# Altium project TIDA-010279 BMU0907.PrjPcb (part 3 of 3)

## Sheet TIDA-010279 BMU_CAN MCU.SchDoc
size 558 x 431 mm; Date: Not shown in title block; ApprovedBy: Not shown in title block; CheckedBy: Not shown in title block; Author: Not shown in title block; CompanyName: Not shown in title block; Engineer: Not shown in title block; Organization: Not shown in title block; Address1: Not shown in title block; Address2: Not shown in title block; Address3: Not shown in title block; Address4: Not shown in title block; DocumentNumber: 1; Revision: Use project parameter SCH_Rev; SheetNumber: 4; SheetTotal: 4; PageSetup: Record=PageOptions¦CenterHorizontal=True¦CenterVertical=True¦PrintScale=1.00¦XCorrection=1.00¦YCorrection=1.00¦PrintKind=0¦BorderSize=5000000¦LeftOffset=0¦BottomOffset=0¦Orientation=2¦PaperLength=1000¦PaperWidth=1000¦Scale=100¦PaperSource=15¦PrintQuality=600¦MediaType=1¦DitherType=10¦PaperKind=Letter¦PrintScaleMode=1
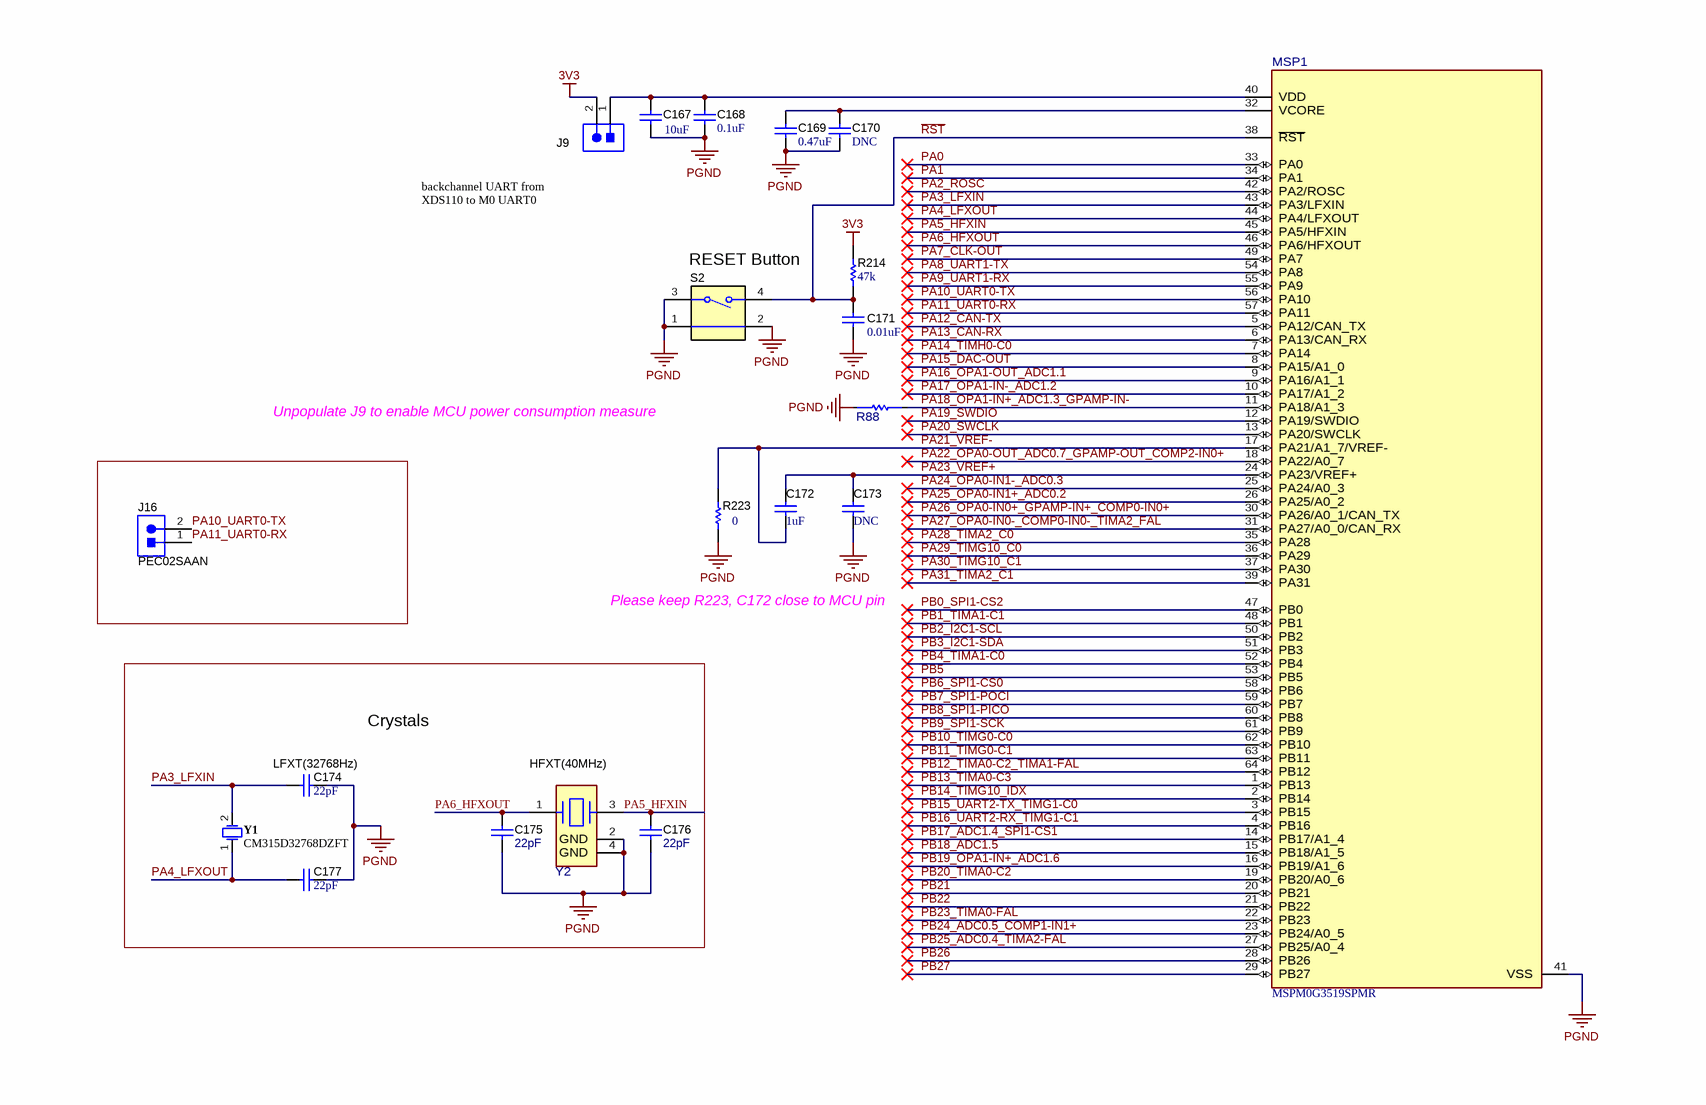
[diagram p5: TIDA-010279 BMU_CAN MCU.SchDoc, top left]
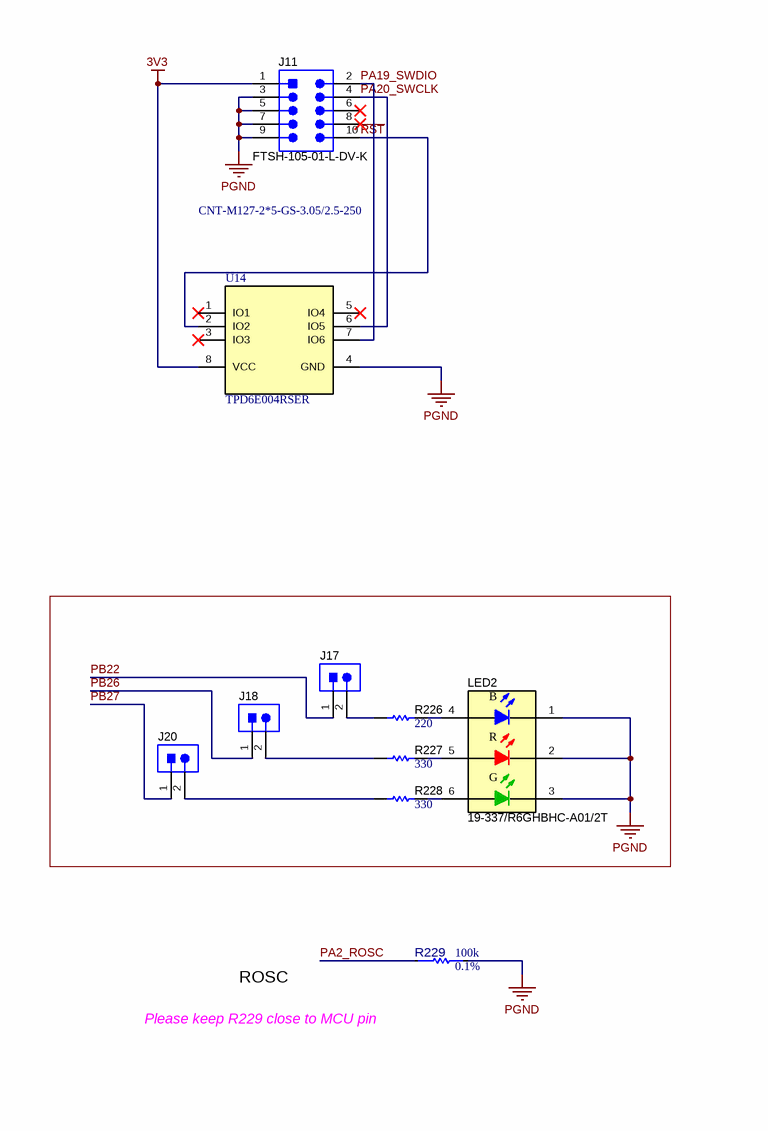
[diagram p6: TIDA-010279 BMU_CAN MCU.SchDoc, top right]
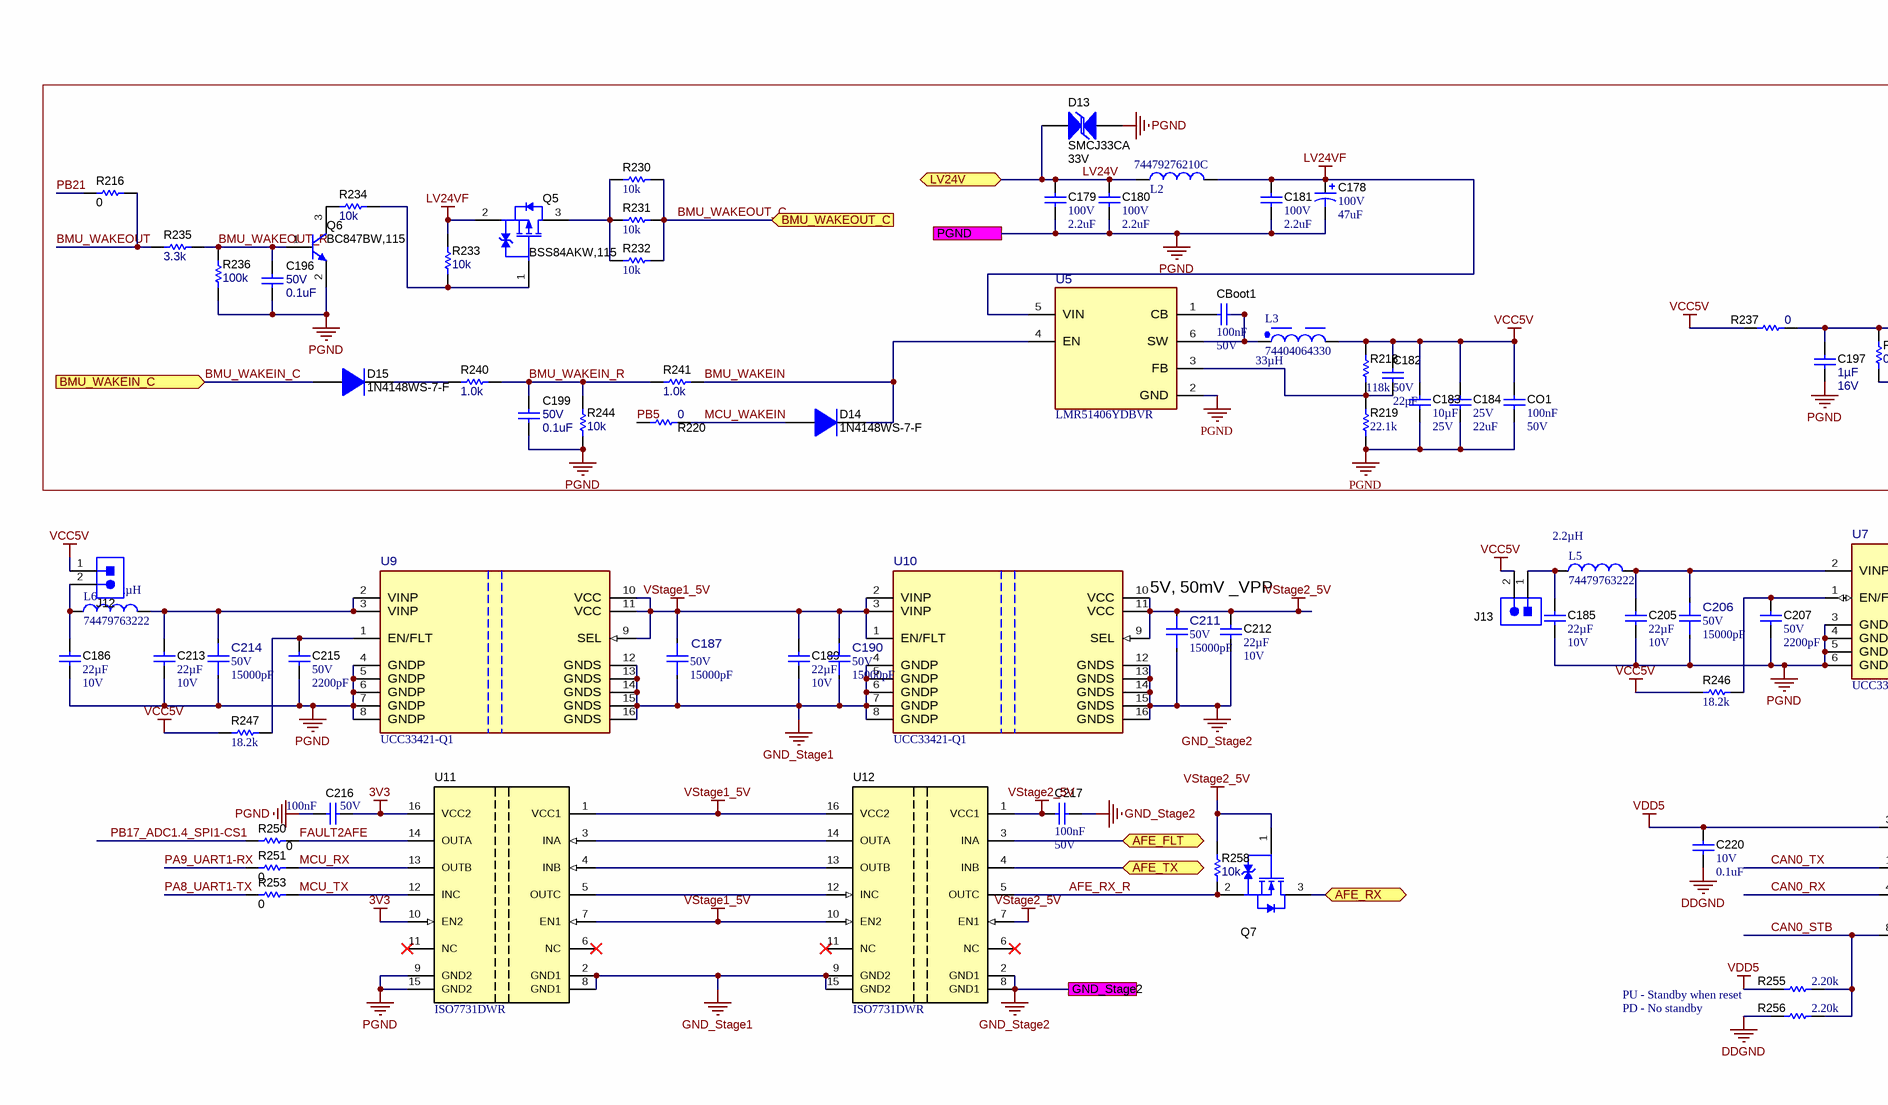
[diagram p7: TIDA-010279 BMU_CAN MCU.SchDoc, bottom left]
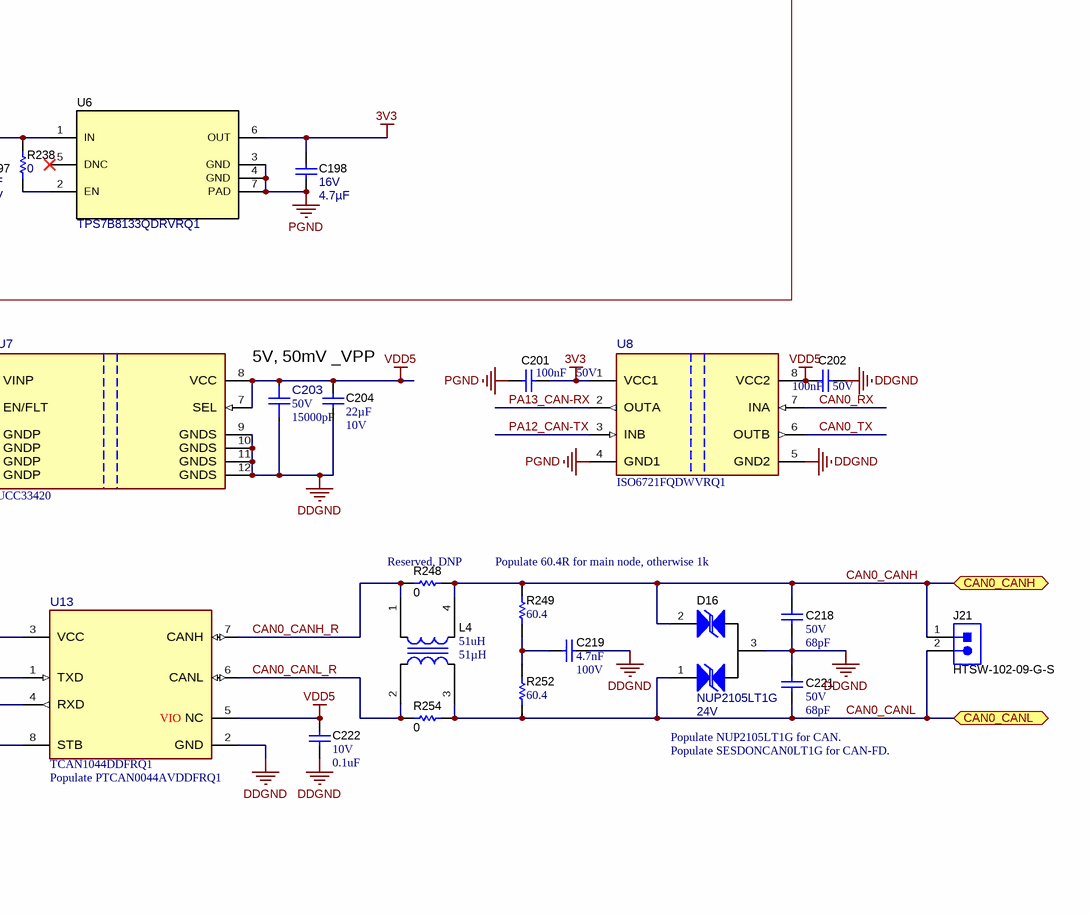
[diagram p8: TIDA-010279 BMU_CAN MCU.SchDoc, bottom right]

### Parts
C167  ValueDisplayed: 10uF  [0603]  (hidden comment: GRM188R60J106ME84)
C168  ValueDisplayed: 0.1uF  [0402]  (hidden comment: GRM155R61H104ME14D)
C169  ValueDisplayed: 0.47uF  [0402]  (hidden comment: GRM155R60J474KE19D)
C170  ValueDisplayed: DNC  [0402]  (hidden comment: GRM155R61H104ME14D)  (no BOM)
C171  ValueDisplayed: 0.01uF  [0402]  (hidden comment: GRM155R61C103KA01D)
C172  value 1uF  [0603]  (hidden comment: C1608X5R1E105K080AC)
C173  ValueDisplayed: DNC  [0603]  (hidden comment: C1608X5R1E105K080AC)  (no BOM)
C174  ValueDisplayed: 22pF  [0402]  (hidden comment: GRM1555C1H220JA01D)
C175  ValueDisplayed: 22pF  [0402]  (hidden comment: GRM1555C1H220JA01D)
C176  ValueDisplayed: 22pF  [0402]  (hidden comment: GRM1555C1H220JA01D)
C177  ValueDisplayed: 22pF  [0402]  (hidden comment: GRM1555C1H220JA01D)
C178  VDC_V: 100V  ValueDisplayed: 47uF  [Panasonic_H13]  (hidden comment: EEV-TG2A470Q)
C179  VDC_V: 100V  ValueDisplayed: 2.2uF  [1206_180]  (hidden comment: C3216X7S2A225K160AB)
C180  VDC_V: 100V  ValueDisplayed: 2.2uF  [1206_180]  (hidden comment: C3216X7S2A225K160AB)
C181  VDC_V: 100V  ValueDisplayed: 2.2uF  [1206_180]  (hidden comment: C3216X7S2A225K160AB)
C182  value 22pF  VDC_V: 50V  [0603]  (hidden comment: CGA3E2C0G1H220J080AA)
C183  Cap_F: 10µF  VDC_V: 25V  [0805_HV]  (hidden comment: GRM21BZ71E106KE15L)
C184  VDC_V: 25V  ValueDisplayed: 22uF  [1812_280]  (hidden comment: CGA8P1X7R1E226M250KC)
C185  Cap_F: 22µF  VDC_V: 10V  [0805_HV]  (hidden comment: GRM21BZ71A226ME15L)
C186  Cap_F: 22µF  VDC_V: 10V  [0805_HV]  (hidden comment: GRM21BZ71A226ME15L)
C187  VDC_V: 50V  ValueDisplayed: 15000pF  [FP-GCM155R71H153KA55D_0402-MFG]  (hidden comment: GCM155R71H153KA55D)
C189  Cap_F: 22µF  VDC_V: 10V  [0805_HV]  (hidden comment: GRM21BZ71A226ME15L)
C190  VDC_V: 50V  ValueDisplayed: 15000pF  [FP-GCM155R71H153KA55D_0402-MFG]  (hidden comment: GCM155R71H153KA55D)
C196  VDC_V: 50V  ValueDisplayed: 0.1uF  [0402]  (hidden comment: GCM155R71H104KE02D)
C197  Cap_F: 1µF  VDC_V: 16V  [0603]  (hidden comment: GCM188R71C105KA64D)
C198  VDC_V: 16V  ValueDisplayed: 4.7µF  [0603]  (hidden comment: GRT188R61C475KE13D)
C199  VDC_V: 50V  ValueDisplayed: 0.1uF  [0402]  (hidden comment: GCM155R71H104KE02D)
C201  Cap_F: 100nF  VDC_V: 50V  [0603]  (hidden comment: 06035C104KAT2A)
C202  Cap_F: 100nF  VDC_V: 50V  [0603]  (hidden comment: 06035C104KAT2A)
C203  VDC_V: 50V  ValueDisplayed: 15000pF  [FP-GCM155R71H153KA55D_0402-MFG]  (hidden comment: GCM155R71H153KA55D)
C204  Cap_F: 22µF  VDC_V: 10V  [0805_HV]  (hidden comment: GRM21BZ71A226ME15L)
C205  Cap_F: 22µF  VDC_V: 10V  [0805_HV]  (hidden comment: GRM21BZ71A226ME15L)
C206  VDC_V: 50V  ValueDisplayed: 15000pF  [FP-GCM155R71H153KA55D_0402-MFG]  (hidden comment: GCM155R71H153KA55D)
C207  VDC_V: 50V  ValueDisplayed: 2200pF  [0402]  (hidden comment: GCM155R71H222KA37D)
C211  VDC_V: 50V  ValueDisplayed: 15000pF  [FP-GCM155R71H153KA55D_0402-MFG]  (hidden comment: GCM155R71H153KA55D)
C212  Cap_F: 22µF  VDC_V: 10V  [0805_HV]  (hidden comment: GRM21BZ71A226ME15L)
C213  Cap_F: 22µF  VDC_V: 10V  [0805_HV]  (hidden comment: GRM21BZ71A226ME15L)
C214  VDC_V: 50V  ValueDisplayed: 15000pF  [FP-GCM155R71H153KA55D_0402-MFG]  (hidden comment: GCM155R71H153KA55D)
C215  VDC_V: 50V  ValueDisplayed: 2200pF  [0402]  (hidden comment: GCM155R71H222KA37D)
C216  Cap_F: 100nF  VDC_V: 50V  [0603]  (hidden comment: 06035C104KAT2A)
C217  Cap_F: 100nF  VDC_V: 50V  [0603]  (hidden comment: 06035C104KAT2A)
C218  VDC_V: 50V  ValueDisplayed: 68pF  [0603]  (hidden comment: GCM1885C1H680JA16D)
C219  Cap_F: 4.7nF  VDC_V: 100V  [0603]  (hidden comment: GCM188R72A472KA37D)
C220  VDC_V: 10V  ValueDisplayed: 0.1uF  [0402]  (hidden comment: GCM155R71A104KA55D)
C221  VDC_V: 50V  ValueDisplayed: 68pF  [0603]  (hidden comment: GCM1885C1H680JA16D)
C222  VDC_V: 10V  ValueDisplayed: 0.1uF  [0402]  (hidden comment: GCM155R71A104KA55D)
CBoot1  Cap_F: 100nF  VDC_V: 50V  [0603]  (hidden comment: 06035C104KAT2A)
CO1  Cap_F: 100nF  VDC_V: 50V  [0805_HV]  (hidden comment: 08055C104JAT2A)
D13  SMCJ33CA  value 33V  [SMC_Bi]
D14  1N4148WS-7-F  [SOD-323]
D15  1N4148WS-7-F  [SOD-323]
D16  NUP2105LT1G  value 24V  [SOT-23]
J9  90120-0122  [CONN_90120-0122]  (value not drawn)
J11  FTSH-105-01-L-DV-K  [Samtec_FTSH-105-01-x-DV-K]
J12  90120-0122  [CONN_90120-0122]  (value not drawn)
J13  90120-0122  [CONN_90120-0122]  (value not drawn)
J16  PEC02SAAN  [CONN_PEC02SAAN]
J17  90120-0122  [CONN_90120-0122]  (value not drawn)
J18  90120-0122  [CONN_90120-0122]  (value not drawn)
J20  90120-0122  [CONN_90120-0122]  (value not drawn)
J21  HTSW-102-09-G-S  [Samtec_HTSW-102-09-x-S]
L2  74479276210C  [WE-PMCI_0806_L2W1.6H1]
L3  74404064330  Inductance: 33µH  [WE-LQS_6045]
L4  value 51uH  ValueDisplayed: 51µH  [ACT45B_NoSilk]  (hidden comment: ACT45B-510-2P-TL003)
L5  74479763222  Inductance: 2.2µH  [WE-PMI_0603_L1.6W0.8H0.8]
L6  74479763222  Inductance: 2.2µH  [WE-PMI_0603_L1.6W0.8H0.8]
LED2  19-337/R6GHBHC-A01/2T  [19-337_RGB]
MSP1  PartNumber: MSPM0G3519SPMR  [PM0064A-MFG]  (hidden comment: MSPM0G3507SPM)
Q5  BSS84AKW,115  [SOT-323]
Q6  BC847BW,115  [SOT-323]
Q7  RE1C002UNTCL  [SC-89]  (value not drawn)
R88  ERJ-2GEJ473X  [FP-ERJ-2GEJ473X_0402-MFG]  (value not drawn)
R214  ValueDisplayed: 47k  [0402]  (hidden comment: CRCW040247K0JNED)
R216  ValueDisplayed: 0  [0402]  (hidden comment: CRCW04020000Z0ED)
R218  ValueDisplayed: 118k  [0402]  (hidden comment: CRCW0402118KFKED)
R219  ValueDisplayed: 22.1k  [0402]  (hidden comment: CRCW040222K1FKED)
R220  ValueDisplayed: 0  [0603]  (hidden comment: CRCW06030000Z0EA)
R223  value 0  [0603]  (hidden comment: RC0603JR-070RL)
R226  ValueDisplayed: 220  [0402]  (hidden comment: CRCW0402220RJNED)
R227  ValueDisplayed: 330  [0402]  (hidden comment: CRCW0402330RJNED)
R228  ValueDisplayed: 330  [0402]  (hidden comment: CRCW0402330RJNED)
R229  Tolerance_%: 0.1%  Res_ohm: 100k  [FP-ERA-2AEB104X_0402-MFG]  (hidden comment: ERA-2AEB104X)
R230  ValueDisplayed: 10k  [0603]  (hidden comment: CRCW060310K0JNEA)
R231  ValueDisplayed: 10k  [0603]  (hidden comment: CRCW060310K0JNEA)
R232  ValueDisplayed: 10k  [0603]  (hidden comment: CRCW060310K0JNEA)
R233  ValueDisplayed: 10k  [0402]  (hidden comment: CRCW040210K0JNED)
R234  ValueDisplayed: 10k  [0402]  (hidden comment: CRCW040210K0JNED)
R235  ValueDisplayed: 3.3k  [0402]  (hidden comment: CRCW04023K30JNED)
R236  ValueDisplayed: 100k  [0402]  (hidden comment: CRCW0402100KJNED)
R237  ValueDisplayed: 0  [0603]  (hidden comment: CRCW06030000Z0EA)
R238  ValueDisplayed: 0  [0603]  (hidden comment: CRCW06030000Z0EA)
R240  ValueDisplayed: 1.0k  [0402]  (hidden comment: CRCW04021K00JNED)
R241  ValueDisplayed: 1.0k  [0402]  (hidden comment: CRCW04021K00JNED)
R244  ValueDisplayed: 10k  [0402]  (hidden comment: CRCW040210K0JNED)
R246  ValueDisplayed: 18.2k  [0603]  (hidden comment: CRCW060318K2FKEA)
R247  ValueDisplayed: 18.2k  [0603]  (hidden comment: CRCW060318K2FKEA)
R248  ValueDisplayed: 0  [0402]  (hidden comment: CRCW04020000Z0ED)
R249  ValueDisplayed: 60.4  [1206]  (hidden comment: ERJ-8ENF60R4V)
R250  ValueDisplayed: 0  [0402]  (hidden comment: CRCW04020000Z0ED)
R251  ValueDisplayed: 0  [0402]  (hidden comment: CRCW04020000Z0ED)
R252  ValueDisplayed: 60.4  [1206]  (hidden comment: ERJ-8ENF60R4V)
R253  ValueDisplayed: 0  [0402]  (hidden comment: CRCW04020000Z0ED)
R254  ValueDisplayed: 0  [0402]  (hidden comment: CRCW04020000Z0ED)
R255  ValueDisplayed: 2.20k  [0402]  (hidden comment: ERJ-2RKF2201X)
R256  ValueDisplayed: 2.20k  [0402]  (hidden comment: ERJ-2RKF2201X)
R258  ValueDisplayed: 10k  [0402]  (hidden comment: CRCW040210K0JNED)
S2  1188E-1K2-V-TR  [SW_1188E]  (value not drawn)
U5  PartNumber: LMR51406YDBVR  [DBV0006A-MFG]  (hidden comment: LMR51410YDBVR)
U6  TPS7B8133QDRVRQ1  [DRV0006A]
U7  UCC33420  [RAQ0012B-MFG]
U8  ISO6721FQDWVRQ1  [DWV0008A-MFG]
U9  UCC33421-Q1  [DWX0016A-MFG]
U10  UCC33421-Q1  [DWX0016A-MFG]
U11  ISO7731DWR  [DW0016B_HV]
U12  ISO7731DWR  [DW0016B_HV]
U13  TCAN1044DDFRQ1  [DDF0008A-MFG]
U14  TPD6E004RSER  [RSE0008A]
Y1  CM315D32768DZFT  [CMHT-CM315D-2_V]
Y2  X1E0000210179  [FP-X1E0000210179_TSX-3225-MFG]  (value not drawn)

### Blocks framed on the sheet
Crystals: C174-C177 Y1 Y2

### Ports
AFE_FLT (bidir), AFE_RX (bidir), AFE_TX (bidir), BMU_WAKEIN_C (in), BMU_WAKEOUT_C (in), CAN0_CANH (bidir), CAN0_CANL (bidir), GND_Stage2, LV24V (bidir), PGND

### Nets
3V3: C198.1 C201.2 C216.1 J9.2 J11.1 R214.2 U6.6(OUT) U8.1(VCC1) U11.10(EN2) U11.16(VCC2) U14.8(VCC)
DDGND: C202.2 C203.1 C204.2 C218.2 C219.2 C220.1 C221.1 C222.2 D16.3 R256.2 U7.9(GNDS) U7.10(GNDS) U7.11(GNDS) U7.12(GNDS) U8.5(GND2) U13.2(GND)
GND_Stage1: C187.1 C189.2 C190.1 U9.12(GNDS) U9.13(GNDS) U9.14(GNDS) U9.15(GNDS) U9.16(GNDS) U10.4(GNDP) U10.5(GNDP) U10.6(GNDP) U10.7(GNDP) U10.8(GNDP) U11.2(GND1) U11.8(GND1) U12.9(GND2) U12.15(GND2)
GND_Stage2: C211.1 C212.2 C217.1 U10.12(GNDS) U10.13(GNDS) U10.14(GNDS) U10.15(GNDS) U10.16(GNDS) U12.2(GND1) U12.8(GND1) ; port GND_Stage2
LV24VF: C178.1(+) C181.1 L2.2 Q5.2(S) R233.2 U5.5(VIN)
PGND: C167.2 C168.2 C169.2 C170.2 C171.2 C173.2 C174.1 C175.1 C176.1 C177.1 C178.2(-) C179.2 C180.2 C181.2 C183.2 C184.2 C185.2 C186.2 C196.2 C197.2 C198.2 C199.2 C201.1 C205.2 C206.1 C207.2 C213.2 C214.1 C215.2 C216.2 CO1.2 D13.1 J11.3 J11.5 J11.7 J11.9 LED2.1(K) LED2.2(K) LED2.3(K) MSP1.41(VSS) Q6.2(E) R88.1 R219.1 R223.1 R229.2 R236.1 R244.1 S2.1 S2.2 S2.3 U5.2(GND) U6.3(GND) U6.4(GND) U6.7(PAD) U7.3(GNDP) U7.4(GNDP) U7.5(GNDP) U7.6(GNDP) U8.4(GND1) U9.4(GNDP) U9.5(GNDP) U9.6(GNDP) U9.7(GNDP) U9.8(GNDP) U11.9(GND2) U11.15(GND2) U14.4(GND) Y2.2(GND) Y2.4(GND) ; port PGND
VCC5V: C182.1 C183.1 C184.1 CO1.1 J12.1 J13.2 L3.2 R218.2 R237.1 R246.1 R247.1
VDD5: C202.1 C203.2 C204.1 C220.2 C222.1 R255.2 U7.7(SEL) U7.8(VCC) U8.8(VCC2) U13.3(VCC) U13.5(NC)
VStage1_5V: C187.2 C189.1 C190.2 U9.9(SEL) U9.10(VCC) U9.11(VCC) U10.1(EN/FLT) U10.2(VINP) U10.3(VINP) U11.1(VCC1) U11.7(EN1) U12.10(EN2) U12.16(VCC2)
VStage2_5V: C211.2 C212.1 C217.2 Q7.1(G) R258.2 U10.9(SEL) U10.10(VCC) U10.11(VCC) U12.1(VCC1) U12.7(EN1)
AFE_FLT: U12.3(INA) ; port AFE_FLT
AFE_RX: Q7.3(D) ; port AFE_RX
AFE_RX_R: Q7.2(S) R258.1 U12.5(OUTC)
AFE_TX: U12.4(INB) ; port AFE_TX
BMU_WAKEIN: D14.1(K) R241.2 U5.4(EN)
BMU_WAKEIN_C: D15.2(A) ; port BMU_WAKEIN_C
BMU_WAKEIN_R: C199.1 R240.2 R241.1 R244.2
BMU_WAKEOUT: R216.2 R235.1
BMU_WAKEOUT_C: R230.2 R231.2 R232.2 ; port BMU_WAKEOUT_C
BMU_WAKEOUT_R: C196.1 Q6.1(B) R235.2 R236.2
CAN0_CANH: C218.1 D16.2 J21.1 L4.4 R248.2 R249.2 ; port CAN0_CANH
CAN0_CANH_R: L4.1 R248.1 U13.7(CANH)
CAN0_CANL: C221.2 D16.1 J21.2 L4.3 R252.1 R254.2 ; port CAN0_CANL
CAN0_CANL_R: L4.2 R254.1 U13.6(CANL)
CAN0_RX: U8.7(INA) U13.4(RXD)
CAN0_STB: R255.1 R256.1 U13.8(STB)
CAN0_TX: U8.6(OUTB) U13.1(TXD)
FAULT2AFE: R250.1 U11.14(OUTA)
LV24V: C179.1 C180.1 D13.2 L2.1 ; port LV24V
MCU_RX: R251.2 U11.13(OUTB)
MCU_TX: R253.2 U11.12(INC)
MCU_WAKEIN: D14.2(A) R220.2
PA0: MSP1.33(PA0)
PA1: MSP1.34(PA1)
PA2_ROSC: MSP1.42(PA2/ROSC) R229.1
PA3_LFXIN: C174.2 MSP1.43(PA3/LFXIN) Y1.2
PA4_LFXOUT: C177.2 MSP1.44(PA4/LFXOUT) Y1.1
PA5_HFXIN: C176.2 MSP1.45(PA5/HFXIN) Y2.3
PA6_HFXOUT: C175.2 MSP1.46(PA6/HFXOUT) Y2.1
PA7_CLK-OUT: MSP1.49(PA7)
PA8_UART1-TX: MSP1.54(PA8) R253.1
PA9_UART1-RX: MSP1.55(PA9) R251.1
PA10_UART0-TX: J16.2 MSP1.56(PA10)
PA11_UART0-RX: J16.1 MSP1.57(PA11)
PA12_CAN-TX: MSP1.5(PA12/CAN_TX) U8.3(INB)
PA13_CAN-RX: MSP1.6(PA13/CAN_RX) U8.2(OUTA)
PA14_TIMH0-C0: MSP1.7(PA14)
PA15_DAC-OUT: MSP1.8(PA15/A1_0)
PA16_OPA1-OUT_ADC1.1: MSP1.9(PA16/A1_1)
PA17_OPA1-IN-_ADC1.2: MSP1.10(PA17/A1_2)
PA18_OPA1-IN+_ADC1.3_GPAMP-IN-: MSP1.11(PA18/A1_3) R88.2
PA19_SWDIO: J11.2 MSP1.12(PA19/SWDIO) U14.7(IO6)
PA20_SWCLK: J11.4 MSP1.13(PA20/SWCLK) U14.6(IO5)
PA21_VREF-: C172.2 MSP1.17(PA21/A1_7/VREF-) R223.2
PA22_OPA0-OUT_ADC0.7_GPAMP-OUT_COMP2-IN0+: MSP1.18(PA22/A0_7)
PA23_VREF+: C172.1 C173.1 MSP1.24(PA23/VREF+)
PA24_OPA0-IN1-_ADC0.3: MSP1.25(PA24/A0_3)
PA25_OPA0-IN1+_ADC0.2: MSP1.26(PA25/A0_2)
PA26_OPA0-IN0+_GPAMP-IN+_COMP0-IN0+: MSP1.30(PA26/A0_1/CAN_TX)
PA27_OPA0-IN0-_COMP0-IN0-_TIMA2_FAL: MSP1.31(PA27/A0_0/CAN_RX)
PA28_TIMA2_C0: MSP1.35(PA28)
PA29_TIMG10_C0: MSP1.36(PA29)
PA30_TIMG10_C1: MSP1.37(PA30)
PA31_TIMA2_C1: MSP1.39(PA31)
PB0_SPI1-CS2: MSP1.47(PB0)
PB1_TIMA1-C1: MSP1.48(PB1)
PB2_I2C1-SCL: MSP1.50(PB2)
PB3_I2C1-SDA: MSP1.51(PB3)
PB4_TIMA1-C0: MSP1.52(PB4)
PB5: MSP1.53(PB5) R220.1
PB6_SPI1-CS0: MSP1.58(PB6)
PB7_SPI1-POCI: MSP1.59(PB7)
PB8_SPI1-PICO: MSP1.60(PB8)
PB9_SPI1-SCK: MSP1.61(PB9)
PB10_TIMG0-C0: MSP1.62(PB10)
PB11_TIMG0-C1: MSP1.63(PB11)
PB12_TIMA0-C2_TIMA1-FAL: MSP1.64(PB12)
PB13_TIMA0-C3: MSP1.1(PB13)
PB14_TIMG10_IDX: MSP1.2(PB14)
PB15_UART2-TX_TIMG1-C0: MSP1.3(PB15)
PB16_UART2-RX_TIMG1-C1: MSP1.4(PB16)
PB17_ADC1.4_SPI1-CS1: MSP1.14(PB17/A1_4) R250.2
PB18_ADC1.5: MSP1.15(PB18/A1_5)
PB19_OPA1-IN+_ADC1.6: MSP1.16(PB19/A1_6)
PB20_TIMA0-C2: MSP1.19(PB20/A0_6)
PB21: MSP1.20(PB21) R216.1
PB22: J17.1 MSP1.21(PB22)
PB23_TIMA0-FAL: MSP1.22(PB23)
PB24_ADC0.5_COMP1-IN1+: MSP1.23(PB24/A0_5)
PB25_ADC0.4_TIMA2-FAL: MSP1.27(PB25/A0_4)
PB26: J18.1 MSP1.28(PB26)
PB27: J20.1 MSP1.29(PB27)
~{RST}: C171.1 J11.10 MSP1.38(~{RST}) R214.1 S2.4 U14.2(IO2)
NetC167_1: C167.1 C168.1 J9.1 MSP1.40(VDD)
NetC169_1: C169.1 C170.1 MSP1.32(VCORE)
NetC182_2: C182.2 R218.1 R219.2 U5.3(FB)
NetC185_1: C185.1 J13.1 L5.1
NetC186_1: C186.1 J12.2 L6.1
NetC197_1: C197.1 R237.2 R238.2 U6.1(IN)
NetC205_1: C205.1 C206.2 L5.2 U7.2(VINP)
NetC207_1: C207.1 R246.2 U7.1(EN/FLT)
NetC213_1: C213.1 C214.2 L6.2 U9.2(VINP) U9.3(VINP)
NetC215_1: C215.1 R247.2 U9.1(EN/FLT)
NetC219_1: C219.1 R249.1 R252.2
NetCBoot1_1: CBoot1.1 U5.1(CB)
NetCBoot1_2: CBoot1.2 L3.1 U5.6(SW)
NetD15_1: D15.1(K) R240.1
NetJ17_2: J17.2 R226.1
NetJ18_2: J18.2 R227.1
NetJ20_2: J20.2 R228.1
NetLED2_4: LED2.4(A) R226.2
NetLED2_5: LED2.5(A) R227.2
NetLED2_6: LED2.6(A) R228.2
NetQ5_1: Q5.1(G) R233.1 R234.1
NetQ5_3: Q5.3(D) R230.1 R231.1 R232.1
NetQ6_3: Q6.3(C) R234.2
NetR238_1: R238.1 U6.2(EN)
NetU11_3: U11.3(INA) U12.14(OUTA)
NetU11_4: U11.4(INB) U12.13(OUTB)
NetU11_5: U11.5(OUTC) U12.12(INC)

Not connected (* = marked no-connect by the designer): J11 6* 8*; U6 5(DNC)*; U11 6(NC)* 11(NC)*; U12 6(NC)* 11(NC)*; U14 1(IO1)* 3(IO3)* 5(IO4)*

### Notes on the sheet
- CNT-M127-2*5-GS-3.05/2.5-250
- backchannel UART from XDS110 to M0 UART0
- (near S2) RESET Button
- Unpopulate J9 to enable MCU power consumption measure
- Please keep R223, C172 close to MCU pin
- (near C174) LFXT(32768Hz)
- HFXT(40MHz)
- Please keep R229 close to MCU pin
- ROSC
- 5V, 50mV _VPP
- (near R248) Reserved, DNP
- (near R249) Populate 60.4R for main node, otherwise 1k
- (near U13) VIO
- (near U13) Populate PTCAN0044AVDDFRQ1
- Populate NUP2105LT1G for CAN.
- Populate SESDONCAN0LT1G for CAN-FD.
- PU - Standby when reset
- PD - No standby

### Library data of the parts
C167 = CMP-0007304-5: CAP, CERM, 10 uF, 6.3 V, +/- 20%, X5R, 0603; Manufacturer: MuRata; TaMin_C: -55°C; Polarized: N; SizeAreaWB_mm2: 4.68; Value1: Unknown; U/M: EA; Value: 10uF; TaMax_C: 85°C; SizeZ_mm: 1; SizeX_mm: 1.6; SizeY_mm: 0.8; Value2: 6.3V; SizeArea_mm2: 1.28; Cap_F: 10µF; AEC Category: Q200
C168 C170 = CMP-0006614-2: CAP, CERM, 0.1 uF, 50 V, +/- 20%, X5R, 0402; Manufacturer: MuRata; TaMin_C: -55°C; Polarized: N; SizeAreaWB_mm2: 3; Value1: Unknown; U/M: EA; Value: 0.1uF; TaMax_C: 85°C; SizeZ_mm: 0.6; SizeX_mm: 1; SizeY_mm: 0.5; Value2: 50V; Cap_F: 100nF; AEC Category: Q200
C169 = CMP-0006551-2: CAP, CERM, 0.47 uF, 6.3 V, +/- 10%, X5R, 0402; Manufacturer: MuRata; TaMin_C: -55°C; Polarized: N; SizeAreaWB_mm2: 3; Value1: Unknown; U/M: EA; Value: 0.47uF; TaMax_C: 85°C; SizeZ_mm: 0.6; SizeX_mm: 1; SizeY_mm: 0.5; Value2: 6.3V; Cap_F: 470nF; AEC Category: Q200
C171 = CMP-0006590-2: CAP, CERM, 0.01 uF, 16 V, +/- 10%, X5R, 0402; Manufacturer: MuRata; TaMin_C: -55°C; Polarized: N; SizeAreaWB_mm2: 3; Value1: Unknown; U/M: EA; Value: 0.01uF; TaMax_C: 85°C; SizeZ_mm: 0.6; SizeX_mm: 1; SizeY_mm: 0.5; Value2: 16V; Cap_F: 10nF; AEC Category: Q200
C172 = CMP-0007006-5: CAP, CERM, 1 uF, 25 V, +/- 10%, X5R, 0603; Manufacturer: TDK; TaMin_C: -55°C; Polarized: N; SizeAreaWB_mm2: 4.68; Value1: Unknown; U/M: EA; TaMax_C: 85°C; SizeZ_mm: 1; SizeX_mm: 1.6; SizeY_mm: 0.8; Value2: 25V; SizeArea_mm2: 1.28; Cap_F: 1µF; AEC Category: Q200; ValueDisplayed: DNC
C173 = CMP-0007006-5: CAP, CERM, 1 uF, 25 V, +/- 10%, X5R, 0603; Manufacturer: TDK; TaMin_C: -55°C; Polarized: N; SizeAreaWB_mm2: 4.68; Value1: Unknown; U/M: EA; Value: 1uF; TaMax_C: 85°C; SizeZ_mm: 1; SizeX_mm: 1.6; SizeY_mm: 0.8; Value2: 25V; SizeArea_mm2: 1.28; Cap_F: 1µF; AEC Category: Q200
C174-C177 = CMP-0006439-2: CAP, CERM, 22 pF, 50 V, +/- 5%, C0G/NP0, 0402; Manufacturer: MuRata; TaMin_C: -55°C; Polarized: N; SizeAreaWB_mm2: 3; Value1: Unknown; U/M: EA; Value: 22pF; TaMax_C: 125°C; SizeZ_mm: 0.6; SizeX_mm: 1; SizeY_mm: 0.5; Value2: 50V; AEC Category: Q200
C178 = CMP-0011227-2: CAP, AL, 47 uF, 100 V, +/- 20%, 0.42 ohm, AEC-Q200 Grade 1, SMD; Manufacturer: Panasonic; TaMin_C: -40°C; ESR_ohm: 4.2d; Polarized: Y; SizeAreaWB_mm2: 240.25; U/M: EA; Value: 47uF; TaMax_C: 125°C; SizeZ_mm: 14; SizeX_mm: 13.5; Cap_Case: 12.5x13.5mm; SizeArea_mm2: 182.25; CompType: Capacitor; Cap_F: 47µF; IRMS_A: 2.5dA; AEC Grade: 1; AEC Category: Q200
C179-C181 = CMP-0008724-2: CAP, CERM, 2.2 uF, 100 V, +/- 10%, X7S, 1206; Manufacturer: TDK; TaMin_C: -55°C; ESR_ohm: 5.718m; Polarized: N; SizeAreaWB_mm2: 10.92; Value1: 0.005718 ohm; U/M: EA; Value: 2.2uF; TaMax_C: 125°C; SizeZ_mm: 1.8; SizeX_mm: 3.2; SizeY_mm: 1.6; SizeArea_mm2: 5.12; Cap_F: 2.2µF; IRMS_A: 3.03632A; AEC Category: Q200
C182 = CMP-0007071-4: CAP, CERM, 22 pF, 50 V, +/- 5%, C0G/NP0, AEC-Q200 Grade 1, 0603; Manufacturer: TDK; TaMin_C: -55°C; Polarized: N; SizeAreaWB_mm2: 4.68; Value1: Unknown; U/M: EA; TaMax_C: 125°C; SizeZ_mm: 1; SizeX_mm: 1.6; SizeY_mm: 0.8; SizeArea_mm2: 1.28; AEC Qualified: Y; AEC Category: Q200
C183 = CMP-0008378-2: CAP, CERM, 10 uF, 25 V, +/- 10%, X7R, 0805; Manufacturer: MuRata; TaMin_C: -55°C; Polarized: N; SizeAreaWB_mm2: 6.75; Value1: Unknown; U/M: EA; Value: 10uF; TaMax_C: 125°C; SizeZ_mm: 1.45; SizeX_mm: 2; SizeY_mm: 1.25; Cap_Case: 0805; SizeArea_mm2: 2.5; AEC Category: Q200
C184 = CMP-0009402-2: CAP, CERM, 22 uF, 25 V, +/- 20%, X7R, AEC-Q200 Grade 1,; Manufacturer: TDK; TaMin_C: -55°C; ESR_ohm: 2.434m; Polarized: N; SizeAreaWB_mm2: 23.1; Value1: 0.002434 ohm; U/M: EA; Value: 22uF; TaMax_C: 125°C; SizeZ_mm: 2.8; SizeX_mm: 4.5; SizeY_mm: 3.2; SizeArea_mm2: 14.4; AEC Qualified: Y; Cap_F: 22µF; IRMS_A: 4.91649A; AEC Grade: 1; AEC Category: Q200
C185 C186 C189 C204 C205 C212 C213 = CMP-0008377-2: CAP, CERM, 22 uF, 10 V, +/- 20%, X7R, 0805; Manufacturer: MuRata; SizeY_mm: 1.25; Cap_Case: 0805; SizeArea_mm2: 2.5; AEC Qualified: N; AEC Category: Q200; ValueDisplayed: 22uF; TaMin_C: -55°C; SizeAreaWB_mm2: 6.75; Value1: Unknown; U/M: EA; Value: 22uF; TaMax_C: 125°C; SizeZ_mm: 1.45; SizeX_mm: 2
C187 C190 C203 C206 C211 C214 = CMP-0090630-1: 0.015µF ±10% 50V Ceramic Capacitor X7R 0402 (1005 Metric); Manufacturer: Murata; SizeZ_mm: 0.55mm; AEC Qualified: Yes; AEC Grade: Grade 1; Value: 15nF; TempCo: 15%
C196 C199 = CMP-0006356-2: CAP, CERM, 0.1 uF, 50 V, +/- 10%, X7R, AEC-Q200 Grade 1, 0402; Manufacturer: MuRata; TaMin_C: -55°C; Polarized: N; SizeAreaWB_mm2: 3; Value1: Unknown; U/M: EA; Value: 0.1uF; TaMax_C: 125°C; SizeZ_mm: 0.6; SizeX_mm: 1; SizeY_mm: 0.5; AEC Qualified: Y; Cap_F: 100nF; AEC Category: Q200
C197 = CMP-0007136-5: CAP, CERM, 1 uF, 16 V, +/- 10%, X7R, AEC-Q200 Grade 1, 0603; Manufacturer: MuRata; TaMin_C: -55°C; Polarized: N; SizeAreaWB_mm2: 4.68; Value1: Unknown; U/M: EA; Value: 1uF; TaMax_C: 125°C; SizeZ_mm: 1; SizeX_mm: 1.6; SizeY_mm: 0.8; SizeArea_mm2: 1.28; AEC Qualified: Y; AEC Category: Q200
C198 = CMP-0081052-1: CAP, CERM, 4.7 µF, 16 V,+/- 10%, X5R, AEC-Q200 Grade 3, 0603; Manufacturer: MuRata; SizeAreaWB_mm2: 4.68; SizeArea_mm2: 1.28; AEC Qualified: Y; AEC Category: Q200; Value: 4.7uF; TaMax_C: 85°C; SizeZ_mm: 1; AEC Grade: 3; Polarized: N; TaMin_C: -55°C; SizeY_mm: 0.8; U/M: EA; SizeX_mm: 1.6
C201 C202 C216 C217 CBoot1 = CMP-0006802-4: CAP, CERM, 0.1 uF, 50 V, +/- 10%, X7R, 0603; Manufacturer: AVX; TaMin_C: -55°C; Polarized: N; SizeAreaWB_mm2: 4.68; Value1: Unknown; U/M: EA; Value: 0.1uF; TaMax_C: 125°C; SizeZ_mm: 1; SizeX_mm: 1.6; SizeY_mm: 0.8; SizeArea_mm2: 1.28; AEC Category: Q200
C207 C215 = CMP-0006357-2: CAP, CERM, 2200 pF, 50 V, +/- 10%, X7R, AEC-Q200 Grade 1, 0402; Manufacturer: MuRata; TaMin_C: -55°C; Polarized: N; SizeAreaWB_mm2: 3; Value1: Unknown; U/M: EA; Value: 2200pF; TaMax_C: 125°C; SizeZ_mm: 0.6; SizeX_mm: 1; SizeY_mm: 0.5; AEC Qualified: Y; Cap_F: 2.2nF; AEC Category: Q200
C218 C221 = CMP-0007129-4: CAP, CERM, 68 pF, 50 V, +/- 5%, C0G/NP0, AEC-Q200 Grade 1, 0603; Manufacturer: MuRata; TaMin_C: -55°C; Polarized: N; SizeAreaWB_mm2: 4.68; Value1: Unknown; U/M: EA; Value: 68pF; TaMax_C: 125°C; SizeZ_mm: 1; SizeX_mm: 1.6; SizeY_mm: 0.8; SizeArea_mm2: 1.28; AEC Qualified: Y; AEC Category: Q200
C219 = CMP-0079247-1: CAP, CERM, 4700 pF, 100 V,+/- 10%, X7R, AEC-Q200 Grade 1, 0603; Manufacturer: MuRata; SizeAreaWB_mm2: 4.68; SizeArea_mm2: 1.28; AEC Qualified: Y; AEC Category: Q200; Value: 4700pF; TaMax_C: 125°C; SizeZ_mm: 1; Polarized: N; TaMin_C: -55°C; SizeY_mm: 0.8; U/M: EA; SizeX_mm: 1.6
C220 C222 = CMP-0006350-2: CAP, CERM, 0.1 uF, 10 V, +/- 10%, X7R, AEC-Q200 Grade 1, 0402; Manufacturer: MuRata; TaMin_C: -55°C; Polarized: N; SizeAreaWB_mm2: 3; Value1: Unknown; U/M: EA; Value: 0.1uF; TaMax_C: 125°C; SizeZ_mm: 0.6; SizeX_mm: 1; SizeY_mm: 0.5; AEC Qualified: Y; Cap_F: 100nF; AEC Category: Q200
CO1 = CMP-0007631-2: CAP, CERM, 0.1 uF, 50 V, +/- 5%, X7R, 0805; Manufacturer: AVX; TaMin_C: -55°C; ESR_ohm: 0.024; Polarized: N; SizeAreaWB_mm2: 6.75; Value1: 0.024 ohm; U/M: EA; Value: 0.1uF; TaMax_C: 125°C; SizeZ_mm: 1.45; SizeX_mm: 2; SizeY_mm: 1.25; Cap_Case: 0805; SizeArea_mm2: 2.5; AEC Category: Q200
D13 = CMP-0005695-3: Diode, TVS, Bi, 33 V, SMC; Manufacturer: Littelfuse; SizeZ_mm: 2.6; Ppk: 1.5kW; Value1: 1500W; AEC Category: Q101; SizeArea_mm2: 50.5686; SizeX_mm: 8.13; SizeAreaWB_mm2: 83.2686; SizeY_mm: 6.22
D14 D15 = CMP-0079597-2: Diode, Switching, 75 V, 0.15 A, AEC-Q101, SOD-323; Manufacturer: Diodes Inc.; SizeX_mm: 2.7; Vf_V: 1.25V; AEC Qualified: Y; SizeArea_mm2: 3.645; AEC Category: Q101; SizeAreaWB_mm2: 8.695; Io_A: 150mA; SizeZ_mm: 1; Value1: 0.15A; SizeY_mm: 1.35; TJmax_C: 150°C; Vr_V: 75V; Value: 75V
D16 = CMP-0005919-3: Diode, TVS, Bi, 24 V, SOT-23; Manufacturer: ON Semiconductor; Value1: 350W; SizeAreaWB_mm2: 14; SizeY_mm: 3; SizeZ_mm: 1.1; SizeX_mm: 2.5; AEC Category: Q101; SizeArea_mm2: 7.5
J9 J12 J13 J17 J18 J20 = CMP-0055312-1: Header, 100mil, 2x1, Tin, TH; Manufacturer: Molex; CNHeader: TRUE; Green_Lifecycle: Active; Green_REACh: Passed; CT: FALSE
J11 = CMP-0075634-2: Header(Shrouded), 1.27mm, 5x2, Gold, SMT; Manufacturer: Samtec; Pitch_mm: 1.27; Gender: Male; Cert_CSA: Y; Current_A: 3.3A; Row_Count: 2
J16 = CMP-0002337-1: Header, 100mil, 2x1, Tin, TH; Manufacturer: Sullins Connector Solutions; CNHeader: TRUE; Current_A: 3A; Green_Lifecycle: Not Set; Shrouded: N; Gender: Male; Green_REACh: Incomplete; Voltage_V: 1.8kV; Row_Count: 1; Pitch_mm: 2.54; CT: FALSE; Cert_UL: Y
J21 = CMP-0075626-1: Header, 100mil, 2x1, Gold, TH; Manufacturer: Samtec; Pitch_mm: 2.54; Gender: Male; Cert_CSA: Y; CT: False; Row_Count: 1
L2 = CMP-0100947-1: WE-PMCI SMT Power Molded Chip Inductor, size 0806, 1uH, 4.4A, 60mOhm; Manufacturer: Wurth Elektronik; Case/Size Code: 0806; DC Resistance: 55mOhm; Saturation Current: 4.25A; Self Resonant Frequency: 95MHz; Type: Low RDC
L3 = CMP-1354-00075-2: NexarPartId: 46948302; Manufacturer: Wurth Elektronik; Tolerance: 20%; Test Frequency: 100kHz; Saturation Current: 1.8A; DC Resistance (DCR): 137mΩ; Max DC Current: 1.45A; Self Resonant Frequency: 12MHz; Series Resistance: 178.1mΩ; Shielding: Shielded; Core Material: Ferrite
L4 = CMP-0076845-1: Coupled inductor, 51 µH, 0.2 A, 1 ohm, AEC-Q200 Grade 0, SMD; Manufacturer: TDK; SizeAreaWB_mm2: 23.1; SizeArea_mm2: 14.4; AEC Qualified: Y; AEC Category: Q200; SizeZ_mm: 3.0; Green_REACh: Passed; AEC Grade: 0; SizeY_mm: 3.2; Green_Lifecycle: Active; DCR_ohm: 1; SizeX_mm: 4.5
L5 L6 = CMP-1392-00025-2: NexarPartId: 38797936; Manufacturer: Wurth Elektronik; DC Resistance (DCR): 300mΩ; Current Rating: 550mA
LED2 = CMP-0074720-2: LED, RGB, TH; Manufacturer: Everlight; Io_A: 25mA; Vr_V: 5V; Tjmax_C: 85°C; Angle: 120.0; Ir_A: 50µA; Vf_V: 3.8V
MSP1 = CMP-0093960-1: Mixed-Signal Microcontrollers With CAN-FD Interface LQFP64; Manufacturer: Texas Instruments; Number Of I2C Channels: 2; Frequency_Fixed: 80MHz; Number Of Cores: 1; Number Of Pwm Channels: 14; Data Bus Width: 32bits; Standoff Height: 0.05mm; SizeZ_mm: 1.6mm; Number Of I/Os: 60; Memory Type: FLASH; Min Supply Voltage: 1.62V; Number Of Adc Channels: 16; Memory Size: 128KBytes; TJmax_C: +130°C; Number Of Uart Channels: 4; Number Of Timers/Counters: 7; Max Supply Voltage: 3.6V; TaMin_C: -40°C; Core Architecture: ARM Cortex-M0+; Interface: I2C,SPI,UART,CAN,LIN,IrDA,SMBus; Ram Size: 32KBytes; AEC Qualified: No; TaMax_C: +125°C
Q5 = CMP-0000013-4: MOSFET, P-CH, -50 V, -0.15 A, AEC-Q101, SOT-323; Manufacturer: Nexperia; Alternate Manufacturer: None; AEC Category: Q101; SizeY_mm: 2.2; Value: -50V; ChMode: Enhancement; ChType: P; QgTyp_nC: 0.26; IdsMax_A: -150mA; Value2: 0.26 nC; SizeZ_mm: 1.1; SizeAreaWB_mm2: 10.24; AEC Qualified: Y; Vgs_V: -20V; SizeArea_mm2: 4.84
Q6 = CMP-0000486-2: Transistor, NPN, 45 V, 0.1 A, AEC-Q101, SOT-323; Manufacturer: NXP Semiconductor; TaMax_C: 150°C; Value2: 800; Value1: 0.1 A; Vcesat1_V: 90mV; SizeX_mm: 2.2; TaMin_C: -65°C; IcRated_A: 1dA; CompType: BJT; SizeZ_mm: 1.1; AEC Qualified: Y; Value: 45 V; SizeArea_mm2: 4.84; NPN: 1; Vceo_V: 45V; PNP: 0; AEC Category: Q101; SizeAreaWB_mm2: 10.24; U/M: EA
Q7 = CMP-0086180-1: MOSFET, N-CH, 20 V, 0.2 A, AEC-Q101, SC-89; Alternate Manufacturer: None; Manufacturer: Rohm; AEC Category: Q101; Value: 20V; SizeY_mm: 1.6; Vgs_V: 8V; SizeArea_mm2: 2.56; SizeAreaWB_mm2: 6.76; Value2: ? nC; ChMode: Enhancement; ChType: N; Value1: ? ohm; SizeZ_mm: 0.8; AEC Qualified: Y; IdsMax_A: 200mA
R88 = CMP-0122885-1: 47 kOhms ±5% 0.1W, 1/10W Chip Resistor 0402 (1005 Metric) Automotive AEC-Q200 Thick Film; Manufacturer: Panasonic; AEC Grade: Grade 0; AEC Qualified: Yes; Power_W: 100mW; Res_ohm: 47k; SizeZ_mm: 0.4mm; TempCo: 200ppm/°C; VDC_V: 50V; Value: 47k
R214 = CMP-0026935-3: RES, 47 k, 5%, 0.063 W, AEC-Q200 Grade 0, 0402; Manufacturer: Vishay-Dale; Power_W: 63mW; TempCo: 200 ppm/C; Value_Code: 47k0; Value: 47k; EIA_Code: E24; SizeX_mm: 1; SizeY_mm: 0.5; SizeZ_mm: 0.6; Value2: 0.063W; AEC Qualified: Y; VDC_V: 50V; AEC Category: Q200; AEC Grade: 0
R216 R248 R250 R251 R253 R254 = CMP-0026822-3: RES, 0, 5%, 0.063 W, AEC-Q200 Grade 0, 0402; Manufacturer: Vishay-Dale; Power_W: 63mW; TempCo: 200 ppm/C; Value_Code: 0000; Value: 0; EIA_Code: E24; SizeX_mm: 1; SizeY_mm: 0.5; SizeZ_mm: 0.6; Value2: 0.063W; AEC Qualified: Y; VDC_V: 50V; AEC Category: Q200
R218 = CMP-0025973-3: RES, 118 k, 1%, 0.063 W, AEC-Q200 Grade 0, 0402; Manufacturer: Vishay-Dale; Power_W: 63mW; TempCo: 100 ppm/C; Value: 118k; EIA_Code: E96; SizeX_mm: 1; SizeY_mm: 0.5; SizeZ_mm: 0.6; Value2: 0.063W; AEC Qualified: Y; VDC_V: 50V; AEC Category: Q200; AEC Grade: 0
R219 = CMP-0026178-2: RES, 22.1 k, 1%, 0.063 W, AEC-Q200 Grade 0, 0402; Manufacturer: Vishay-Dale; Power_W: 63mW; TempCo: 100 ppm/C; Value_Code: 22k1; Value: 22.1k; EIA_Code: E96; SizeX_mm: 1; SizeY_mm: 0.5; SizeZ_mm: 0.6; Value2: 0.063W; AEC Qualified: Y; VDC_V: 50V; AEC Category: Q200; AEC Grade: 0
R220 R237 R238 = CMP-0025697-4: RES, 0, 5%, 0.1 W, AEC-Q200 Grade 0, 0603; Manufacturer: Vishay-Dale; Power_W: 100mW; TempCo: 200 ppm/C; Value_Code: 0000; Value: 0; EIA_Code: E24; SizeX_mm: 1.6; SizeY_mm: 0.8; SizeZ_mm: 1; Value2: 0.1W; SizeArea_mm2: 1.28; AEC Qualified: Y; VDC_V: 75V; AEC Category: Q200
R223 = CMP-0025885-5: RES, 0, 5%, 0.1 W, 0603; Manufacturer: Yageo; Power_W: 100mW; TempCo: 200 ppm/C; Value_Code: 0000; EIA_Code: E24; SizeX_mm: 1.6; SizeZ_mm: 1; Value2: 0.1W; SizeArea_mm2: 1.28; AEC Qualified: N; VDC_V: 75V; AEC Category: Q200; ValueDisplayed: DNC; SizeY_mm: 0.8; SizeAreaWB_mm2: 4.68
R226 = CMP-0026878-3: RES, 220, 5%, 0.063 W, AEC-Q200 Grade 0, 0402; Manufacturer: Vishay-Dale; Power_W: 63mW; TempCo: 200 ppm/C; Value_Code: 220R; Value: 220; EIA_Code: E24; SizeX_mm: 1; SizeY_mm: 0.5; SizeZ_mm: 0.6; Value2: 0.063W; AEC Qualified: Y; VDC_V: 50V; AEC Category: Q200; AEC Grade: 0
R227 R228 = CMP-0026906-3: RES, 330, 5%, 0.063 W, AEC-Q200 Grade 0, 0402; Manufacturer: Vishay-Dale; Power_W: 63mW; TempCo: 200 ppm/C; Value_Code: 330R; Value: 330; EIA_Code: E24; SizeX_mm: 1; SizeY_mm: 0.5; SizeZ_mm: 0.6; Value2: 0.063W; AEC Qualified: Y; VDC_V: 50V; AEC Category: Q200; AEC Grade: 0
R229 = CMP-0088648-1: Res Thin Film 0402 100K Ohm 0.1% 1/16W ±25ppm/°C Molded SMD SMD Punched Carrier T/R; Manufacturer: Panasonic; Category 7542B8484461Ae85: Passive Components; VDC_V: 50V; Category Cd01000Bfc2916C6: Single Components; Power_W: 63mW; Category 5A00970A6D5C81C7: Uncategorized; AEC Qualified: Yes; SizeZ_mm: 0.4mm; Voltage: 25V; AEC Grade: Grade 0; Category 5C6A91606D4187Ad: Resistors
R230-R232 = CMP-0025701-4: RES, 10 k, 5%, 0.1 W, AEC-Q200 Grade 0, 0603; Manufacturer: Vishay-Dale; Power_W: 100mW; TempCo: 200 ppm/C; Value_Code: 10k0; Value: 10k; EIA_Code: E24; SizeX_mm: 1.6; SizeY_mm: 0.8; SizeZ_mm: 1; Value2: 0.1W; SizeArea_mm2: 1.28; AEC Qualified: Y; VDC_V: 75V; AEC Category: Q200; AEC Grade: 0
R233 R234 R244 R258 = CMP-0026825-5: RES, 10 k, 5%, 0.063 W, AEC-Q200 Grade 0, 0402; Manufacturer: Vishay-Dale; Power_W: 63mW; TempCo: 200 ppm/C; Value_Code: 10k0; Value: 10k; EIA_Code: E24; SizeX_mm: 1; SizeY_mm: 0.5; SizeZ_mm: 0.6; Value2: 0.063W; AEC Qualified: Y; VDC_V: 50V; AEC Category: Q200; AEC Grade: 0
R235 = CMP-0026918-5: RES, 3.3 k, 5%, 0.063 W, AEC-Q200 Grade 0, 0402; Manufacturer: Vishay-Dale; Power_W: 63mW; TempCo: 200 ppm/C; Value_Code: 3k30; Value: 3.3k; EIA_Code: E24; SizeX_mm: 1; SizeY_mm: 0.5; SizeZ_mm: 0.6; Value2: 0.063W; AEC Qualified: Y; VDC_V: 50V; AEC Category: Q200; AEC Grade: 0
R236 = CMP-0026823-3: RES, 100 k, 5%, 0.063 W, AEC-Q200 Grade 0, 0402; Manufacturer: Vishay-Dale; Power_W: 63mW; TempCo: 200 ppm/C; Value: 100k; EIA_Code: E24; SizeX_mm: 1; SizeY_mm: 0.5; SizeZ_mm: 0.6; Value2: 0.063W; AEC Qualified: Y; VDC_V: 50V; AEC Category: Q200; AEC Grade: 0
R240 R241 = CMP-0026852-3: RES, 1.0 k, 5%, 0.063 W, AEC-Q200 Grade 0, 0402; Manufacturer: Vishay-Dale; Power_W: 63mW; TempCo: 200 ppm/C; Value_Code: 1k00; Value: 1.0k; EIA_Code: E24; Res_ohm: 1k; SizeX_mm: 1; SizeY_mm: 0.5; SizeZ_mm: 0.6; Value2: 0.063W; AEC Qualified: Y; VDC_V: 50V; AEC Category: Q200; AEC Grade: 0
R246 R247 = CMP-0022097-4: RES, 18.2 k, 1%, 0.1 W, AEC-Q200 Grade 0, 0603; Manufacturer: Vishay-Dale; Power_W: 100mW; TempCo: 100 ppm/C; Value_Code: 18k2; Value: 18.2k; EIA_Code: E96; SizeX_mm: 1.6; SizeY_mm: 0.8; SizeZ_mm: 1; Value2: 0.1W; SizeArea_mm2: 1.28; AEC Qualified: Y; VDC_V: 75V; AEC Category: Q200; AEC Grade: 0
R249 R252 = CMP-0017672-3: RES, 60.4, 1%, 0.25 W, AEC-Q200 Grade 0, 1206; Manufacturer: Panasonic; Power_W: 250mW; TempCo: 100 ppm/C; Value_Code: 60R4; Value: 60.4; EIA_Code: E96; SizeX_mm: 3.2; SizeY_mm: 1.6; SizeZ_mm: 1.35; Value2: 0.25W; SizeArea_mm2: 5.12; AEC Qualified: Y; VDC_V: 200V; AEC Category: Q200; AEC Grade: 0; SizeAreaWB_mm2: 10.92
R255 R256 = CMP-0026681-1: RES, 2.20 k, 1%, 0.1 W, 0402; Manufacturer: Panasonic; Power_W: 100mW; TempCo: 100 ppm/C; Value_Code: 2k20; U/M: EA; Value: 2.20k; Res_ohm: 2.2k; SizeX_mm: 1; SizeY_mm: 0.5; SizeZ_mm: 0.6; Value2: 0.1W; VDC_V: 50V; AEC Category: Q200
S2 = CMP-0002328-1: Switch, SPST, 0.05 A, 12 VDC, SMD; Manufacturer: Diptronics; CurrentRating_mA: 50A; PositionCount: 1; SizeX_mm: 7.8; SizeY_mm: 3.5; SizeArea_mm2: 27.3; VDC_V: 12V; SizeAreaWB_mm2: 53.9
U5 = CMP-0121877-1: SIMPLE SWITCHER® Power Converter, 4-V to 42-V, 1-A Buck Converter, SOT23; Manufacturer: Texas Instruments; SizeZ_mm: 1.45mm; AEC Qualified: No; AEC Grade: NA; Max Duty Cycle: 98%; Max Supply Voltage: 42V; Min Supply Voltage: 4V; Nominal Supply Current: 26.5-420uA; Number Of Outputs: 1; Output Type: AdjustableProgrammable; Output Voltage: 0.8-28V; Standoff Height: 0mm; Switching Frequency: 1.1MHz; TJmax_C: +150°C
U6 = CMP-0860463-2: Automotive 150-mA high-voltage ultra-low-IQ low-dropout (LDO) linear regulator, DRV0006A (WSON-6); Alternate Manufacturer: Texas Instruments; AEC Qualified: Y; SizeY_mm: 2; SizeZ_mm: 0.8; AEC Category: Q200; CompType: IC; SizeArea_mm2: 4; SizeAreaWB_mm2: 9
U7 = CMP-0098322-4: 1.5W, High-Density, >3 kVRMS Isolated DC-DC Converter; Manufacturer: Texas Instruments; SizeZ_mm: 1.05mm; AEC Qualified: No; AEC Grade: NA; Max Supply Voltage: 5.5V; Min Supply Voltage: 4.5V; Number Of Outputs: 1; Output Type: Fixed; Output Voltage: 5V; AEC Category: Q200; CompType: IC
U8 = CMP-0094881-1: General Purpose Reinforced and Basic Dual-Channel Automotive Digital Isolators with Robust EMC; Manufacturer: Texas Instruments; TaMin_C: -40°C; AEC Grade: Grade 1; Interface: LVCMOS; TJmax_C: +150°C; SizeZ_mm: 2.8mm; TaMax_C: +125°C; Max Supply Voltage: 5.5V; Min Supply Voltage: 1.71V; Standoff Height: 0.36mm; AEC Qualified: Yes
U9 U10 = CMP-0120108-2: 1.5W, High-Density, >5 kVRMS Isolated DC-DC Converter; Manufacturer: Texas Instruments; SizeZ_mm: 2.6mm; AEC Qualified: No; Max Supply Voltage: 5.5V; Min Supply Voltage: 4.5V; Number Of Outputs: 1; Output Type: AdjustableProgrammable; Output Voltage: 5/5.5V; Standoff Height: 0.14mm; AEC Category: Q200; CompType: IC
U11 U12 = CMP-0078446-2: High Speed, Robust EMC Triple-Channel Digital Isolators, DW0016B (SOIC-16); Manufacturer: Texas Instruments; AEC Qualified: N; CompType: IC; Rating: Catalog; SizeArea_mm2: 107.12; SizeX_mm: 10.4; SizeAreaWB_mm2: 152.52; AEC Category: Q200; SizeZ_mm: 2.65; SizeY_mm: 10.3
U13 = CMP-0089901-1: Automotive High Speed CAN Transceiver; Manufacturer: Texas Instruments; Min Supply Voltage: 4.5V; TaMin_C: -40°C; AEC Grade: Grade 1; Standoff Height: 0mm; SizeZ_mm: 1.1mm; TaMax_C: +125°C; Max Supply Voltage: 5.5V; Nominal Supply Current: 5-180mA; TJmax_C: +150°C; AEC Qualified: Yes
U14 = CMP-0043125-4: Low-Capacitance 6-Channel +/-15 kV ESD Protection Array for High-Speed Data Interfaces, RSE0008A (UQFN-8); Manufacturer: Texas Instruments; IO Leakage Current(nA): 1; IO Capacitance(Typ)(pF): 1.6; 1394 / Firewire: TRUE; Eco-Plan: Green (RoHS & no Sb/Br); SubFamily: ESD Solution; Breakdown Voltage(Min)(V): 6; IEC 61000-4-2 Air-Gap(+/- kV): 12; IEC 61000-4-2 Contact(+/- kV): 8; AEC Category: Q200; AEC Qualified: N; CompType: IC; SizeAreaWB_mm2: 6.25; SizeArea_mm2: 2.25; SizeX_mm: 1.5; SizeZ_mm: 0.6
Y1 = CMP-2000-05089-1: Turning Fork Crystal Unit, 32.768 KHz, -40 to 85 degC, 2-Pin SMD, RoHS, Tape and Reel; Manufacturer: Citizen Micro HumanTech; Package Version: Rev. 1.4, 09/2012
Y2 = CMP-0098168-2: Crystal 40MHz ±10ppm (Tol) ±20ppm (Stability) 12pF FUND 40Ohm 4-Pin Mini-CSMD T/R; Manufacturer: Seiko Epson; SizeZ_mm: 0.6mm; AEC Qualified: No; Esr: 40

## Sheet TIDA-010279 BMU_Hardware.SchDoc
size 431 x 279 mm; Date: Not shown in title block; ApprovedBy: Not shown in title block; CheckedBy: Not shown in title block; Author: Not shown in title block; CompanyName: Not shown in title block; Engineer: Not shown in title block; Organization: Not shown in title block; Address1: Not shown in title block; Address2: Not shown in title block; Address3: Not shown in title block; Address4: Not shown in title block; DocumentNumber: 3; Revision: Use project parameter SCH_Rev; SheetNumber: 3; SheetTotal: 4; PageSetup: Record=PageOptions¦CenterHorizontal=True¦CenterVertical=True¦PrintScale=1.00¦XCorrection=1.00¦YCorrection=1.00¦PrintKind=0¦BorderSize=5000000¦LeftOffset=0¦BottomOffset=0¦Orientation=2¦PaperLength=1000¦PaperWidth=1000¦Scale=100¦PaperSource=15¦PrintQuality=600¦MediaType=1¦DitherType=10¦PaperKind=Letter¦PrintScaleMode=1
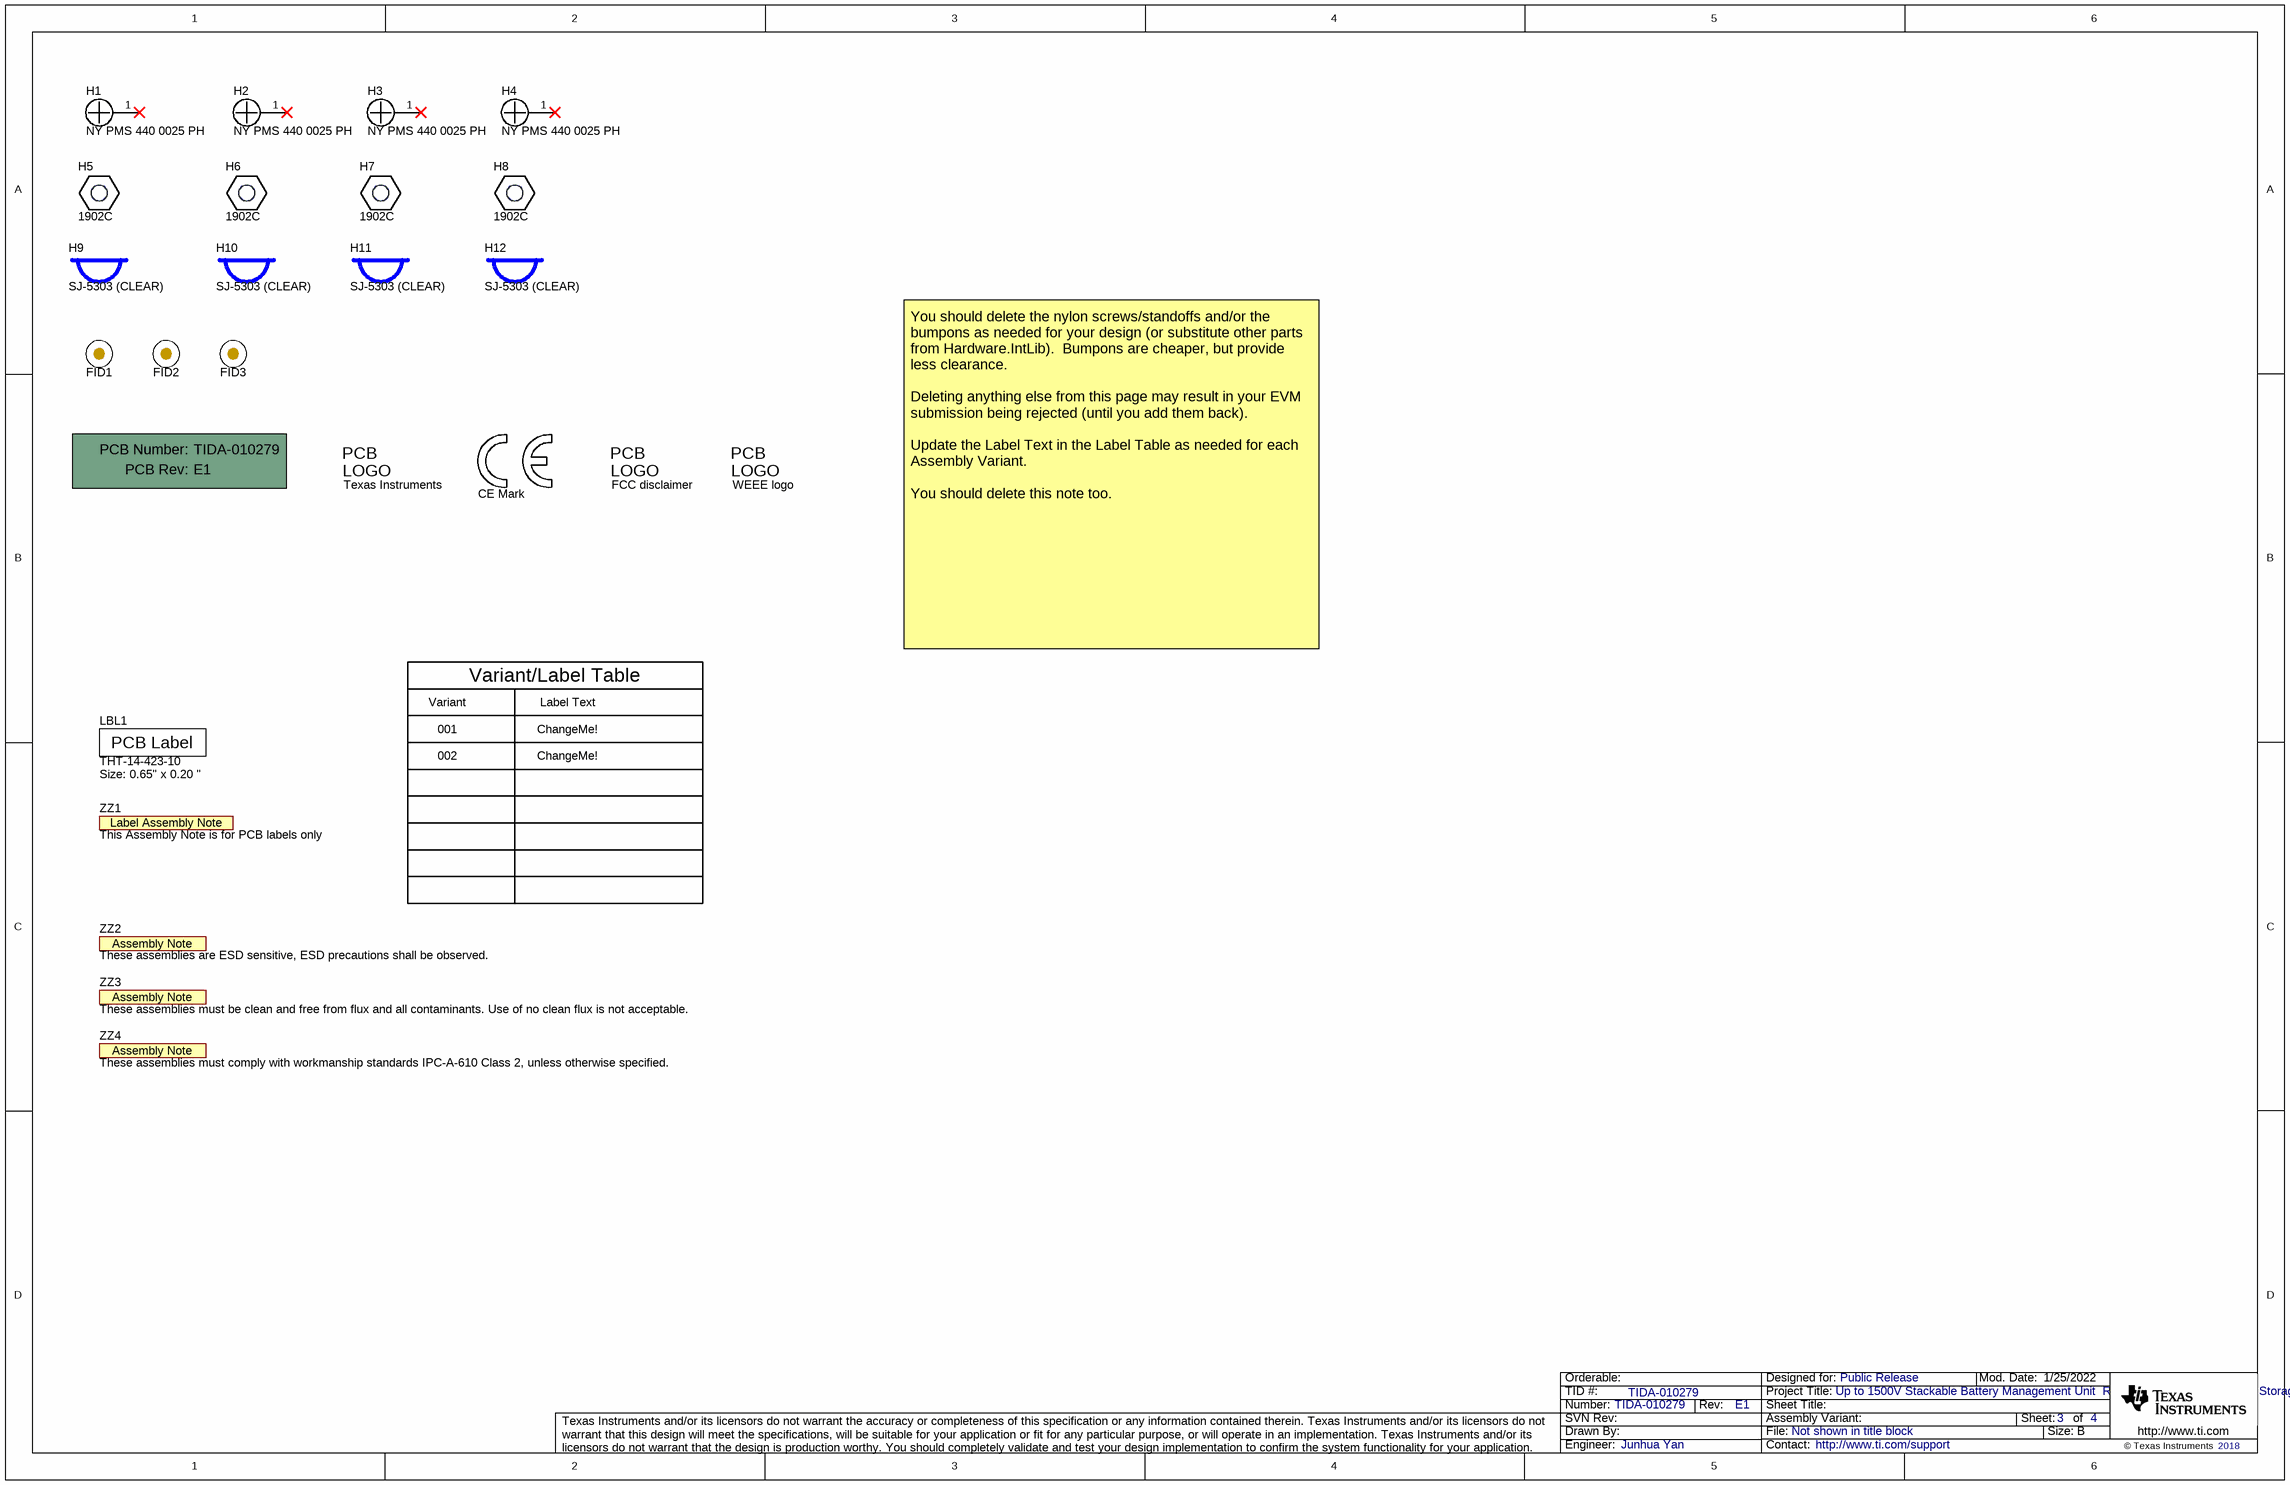
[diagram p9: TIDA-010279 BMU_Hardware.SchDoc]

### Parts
!PCB  Printed Circuit Board  (value not drawn)  (mechanical)
FID1  Fiducial  [Fiducial10-20]  (value not drawn)
FID2  Fiducial  [Fiducial10-20]  (value not drawn)
FID3  Fiducial  [Fiducial10-20]  (value not drawn)
H1  NY PMS 440 0025 PH  [NY PMS 440 0025 PH]
H2  NY PMS 440 0025 PH  [NY PMS 440 0025 PH]
H3  NY PMS 440 0025 PH  [NY PMS 440 0025 PH]
H4  NY PMS 440 0025 PH  [NY PMS 440 0025 PH]
H5  1902C  [Keystone_1902C]
H6  1902C  [Keystone_1902C]
H7  1902C  [Keystone_1902C]
H8  1902C  [Keystone_1902C]
H9  SJ-5303 (CLEAR)  [Bumpon_SJ5003Transparent]
H10  SJ-5303 (CLEAR)  [Bumpon_SJ5003Transparent]
H11  SJ-5303 (CLEAR)  [Bumpon_SJ5003Transparent]
H12  SJ-5303 (CLEAR)  [Bumpon_SJ5003Transparent]
LBL1  THT-14-423-10  Note: Size: 0.65" x 0.20 "  [Label_650x200]
Logo1  Texas Instruments  [TI_Stacked_Overlay_Small]  (no BOM)
Logo2  CE Mark  [CE_Mark_5mm]  (no BOM)
Logo3  FCC disclaimer  [FCC_disclaimer]  (no BOM)
Logo4  WEEE logo  [WEEE_Minimum]  (no BOM)
ZZ1  This Assembly Note is for PCB labels only  [AssemblyNoteLabel]  (no BOM)
ZZ2  These assemblies are ESD sensitive, ESD precautions shall be observed.  [AssemblyNote]  (no BOM)
ZZ3  These assemblies must be clean and free from flux and all contaminants. Use of no clean flux is not acceptable.  [AssemblyNote]  (no BOM)
ZZ4  These assemblies must comply with workmanship standards IPC-A-610 Class 2, unless otherwise specified.  [AssemblyNote]  (no BOM)

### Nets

Not connected (* = marked no-connect by the designer): H1 1*; H2 1*; H3 1*; H4 1*

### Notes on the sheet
- Variant
- Variant/Label Table
- Label Text
- You should delete the nylon screws/standoffs and/or the bumpons as needed for your design (or substitute other parts from Hardware.IntLib).  Bumpons are cheaper, but provide less clearance.
  Deleting anything else from this page may result in your EVM submission being rejected (until you add them back).
  Update the Label Text in the Label Table as needed for each Assembly Variant.
  You should delete this note too.
- 001
- 002
- ChangeMe!

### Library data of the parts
!PCB = CMP-0003618-2: Manufacturer: Any; PartNumber: TIDA-010279
FID1-FID3 = CMP-0077181-1: Fiducial mark.  There is nothing to buy or mount.
H1-H4 = CMP-0003617-1: Machine Screw, Round, #4-40 x 1/4, Nylon, Philips panhead; Manufacturer: B&F Fastener Supply; CompType: Hardware
H5-H8 = CMP-0003610-1: Standoff, Hex, 0.5"L #4-40 Nylon; Manufacturer: Keystone; CompType: Hardware
H9-H12 = CMP-0003620-1: Bumpon, Hemisphere, 0.44 X 0.20, Clear; Manufacturer: 3M
LBL1 = CMP-0003625-1: Thermal Transfer Printable Labels, 0.650" W x 0.200" H - 10,000 per roll; Manufacturer: Brady; CompType: Label
Logo1 = CMP-0074838-1: Texas Instrument Corporate Signature; SymbolCreator: a0412235; Lib Reference: TI_Logo; Library Reference: Logo
Logo2 = CMP-0074844-2: Manufacturer: Texas Instruments; SymbolCreator: a0412235; AEC Category: Q200; CompType: IC
Logo3 = CMP-0074847-1: FCC_disclaimer; Library Reference: Logo
Logo4 = CMP-0074769-4: Manufacturer: Texas Instruments; CompType: IC; AEC Category: Q200
ZZ1 = CMP-0003616-3
ZZ2 = CMP-0077236-1
ZZ3 = CMP-0077237-1
ZZ4 = CMP-0077238-1

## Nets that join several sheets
GND: TIDA-010279 BMU_Schematic_Block (9 pins), A1 (97 pins), A2 (97 pins), A3 (97 pins), A4 (97 pins)
GND_Stage2: TIDA-010279 BMU_Schematic_Block (R211.2), TIDA-010279 BMU_CAN MCU (10 pins)
PGND: TIDA-010279 BMU_Schematic_Block (J5.1 S1.1 S1.2), TIDA-010279 BMU_CAN MCU (69 pins)
AFE_FLT: TIDA-010279 BMU_Schematic_Block (R210.2), TIDA-010279 BMU_CAN MCU (U12.3)
AFE_RX: TIDA-010279 BMU_Schematic_Block (R208.2), TIDA-010279 BMU_CAN MCU (Q7.3)
AFE_TX: TIDA-010279 BMU_Schematic_Block (R209.2), TIDA-010279 BMU_CAN MCU (U12.4)
BMU_WAKEIN_C: TIDA-010279 BMU_Schematic_Block (J5.6 S1.4), TIDA-010279 BMU_CAN MCU (D15.2)
BMU_WAKEOUT_C: TIDA-010279 BMU_Schematic_Block (J5.2), TIDA-010279 BMU_CAN MCU (R230.2 R231.2 R232.2)
CAN0_CANH: TIDA-010279 BMU_Schematic_Block (J5.3 J5.8), TIDA-010279 BMU_CAN MCU (6 pins)
CAN0_CANL: TIDA-010279 BMU_Schematic_Block (J5.4 J5.7), TIDA-010279 BMU_CAN MCU (6 pins)
COMMH_N_OPT: TIDA-010279 BMU_Schematic_Block (C163.1 T2.3), A1 (J4_A1.2 R195_A1.2)
COMMH_N_OPT: TIDA-010279 BMU_Schematic_Block (C164.1 T3.3), A2 (J4_A2.2 R195_A2.2)
COMMH_N_OPT: TIDA-010279 BMU_Schematic_Block (C165.1 T4.3), A3 (J4_A3.2 R195_A3.2)
COMMH_N_OPT: TIDA-010279 BMU_Schematic_Block (T5.6), A4 (J4_A4.2 R195_A4.2)
COMMH_P_OPT: TIDA-010279 BMU_Schematic_Block (C153.2 T2.1), A1 (J4_A1.1 R182_A1.2)
COMMH_P_OPT: TIDA-010279 BMU_Schematic_Block (C154.2 T3.1), A2 (J4_A2.1 R182_A2.2)
COMMH_P_OPT: TIDA-010279 BMU_Schematic_Block (C155.2 T4.1), A3 (J4_A3.1 R182_A3.2)
COMMH_P_OPT: TIDA-010279 BMU_Schematic_Block (T5.4), A4 (J4_A4.1 R182_A4.2)
COMML_N_OPT: TIDA-010279 BMU_Schematic_Block (C163.2 T2.4), A2 (J3_A2.2 R190_A2.1)
COMML_N_OPT: TIDA-010279 BMU_Schematic_Block (C164.2 T3.4), A3 (J3_A3.2 R190_A3.1)
COMML_N_OPT: TIDA-010279 BMU_Schematic_Block (C165.2 T4.4), A4 (J3_A4.2 R190_A4.1)
COMML_N_OPT: TIDA-010279 BMU_Schematic_Block (T1.4), A1 (J3_A1.2 R190_A1.1)
COMML_P_OPT: TIDA-010279 BMU_Schematic_Block (C153.1 T2.6), A2 (J3_A2.1 R177_A2.1)
COMML_P_OPT: TIDA-010279 BMU_Schematic_Block (C154.1 T3.6), A3 (J3_A3.1 R177_A3.1)
COMML_P_OPT: TIDA-010279 BMU_Schematic_Block (C155.1 T4.6), A4 (J3_A4.1 R177_A4.1)
COMML_P_OPT: TIDA-010279 BMU_Schematic_Block (T1.6), A1 (J3_A1.1 R177_A1.1)
LV24V: TIDA-010279 BMU_Schematic_Block (J5.5 S1.3), TIDA-010279 BMU_CAN MCU (C179.1 C180.1 D13.2 L2.1)
NFAULT/GPIO2: TIDA-010279 BMU_Schematic_Block (R210.1), A1 (6 pins)
RX/GPIO0: TIDA-010279 BMU_Schematic_Block (R208.1), A1 (R257_A1.1 U1_A1.51)
TX/GPIO1: TIDA-010279 BMU_Schematic_Block (R209.1), A1 (C110_A1.1 R145_A1.1 U1_A1.52)

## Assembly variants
BQ78706*4: not fitted C157 C158 C159 C160 C161 C162 FID1 FID2 FID3 H9 H10 H11 H12 R196_AFE1 R196_AFE2 R196_AFE3 R196_AFE4 R199_AFE1 R199_AFE2 R199_AFE3 R199_AFE4 R208 R209 R210 R211 R215_A2 R215_A3 R215_A4 R215_AFE1 T2 T3 T4
BQ79718*3: all parts fitted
